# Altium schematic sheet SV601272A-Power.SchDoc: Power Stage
size 431 x 279 mm; Date: Not shown in title block; ApprovedBy: Not shown in title block; CheckedBy: Not shown in title block; Author: Not shown in title block; CompanyName: Not shown in title block; Engineer: Not shown in title block; Organization: Not shown in title block; Address1: Not shown in title block; Address2: Not shown in title block; Address3: Not shown in title block; Address4: Not shown in title block; DocumentNumber: 5; Revision: Use project parameter SCH_Rev; SheetNumber: 5; SheetTotal: 11; PageSetup: Record=PageOptions¦CenterHorizontal=True¦CenterVertical=True¦PrintScale=0.62¦XCorrection=1.00¦YCorrection=1.00¦PrintKind=0¦BorderSize=5000000¦LeftOffset=0¦BottomOffset=0¦Orientation=2¦PaperLength=1000¦PaperWidth=1000¦Scale=100¦PaperSource=15¦PrintQuality=600¦MediaType=1¦DitherType=10¦PrintScaleMode=1¦PaperKind=Letter (8.5 x 11")¦PaperIndex=1
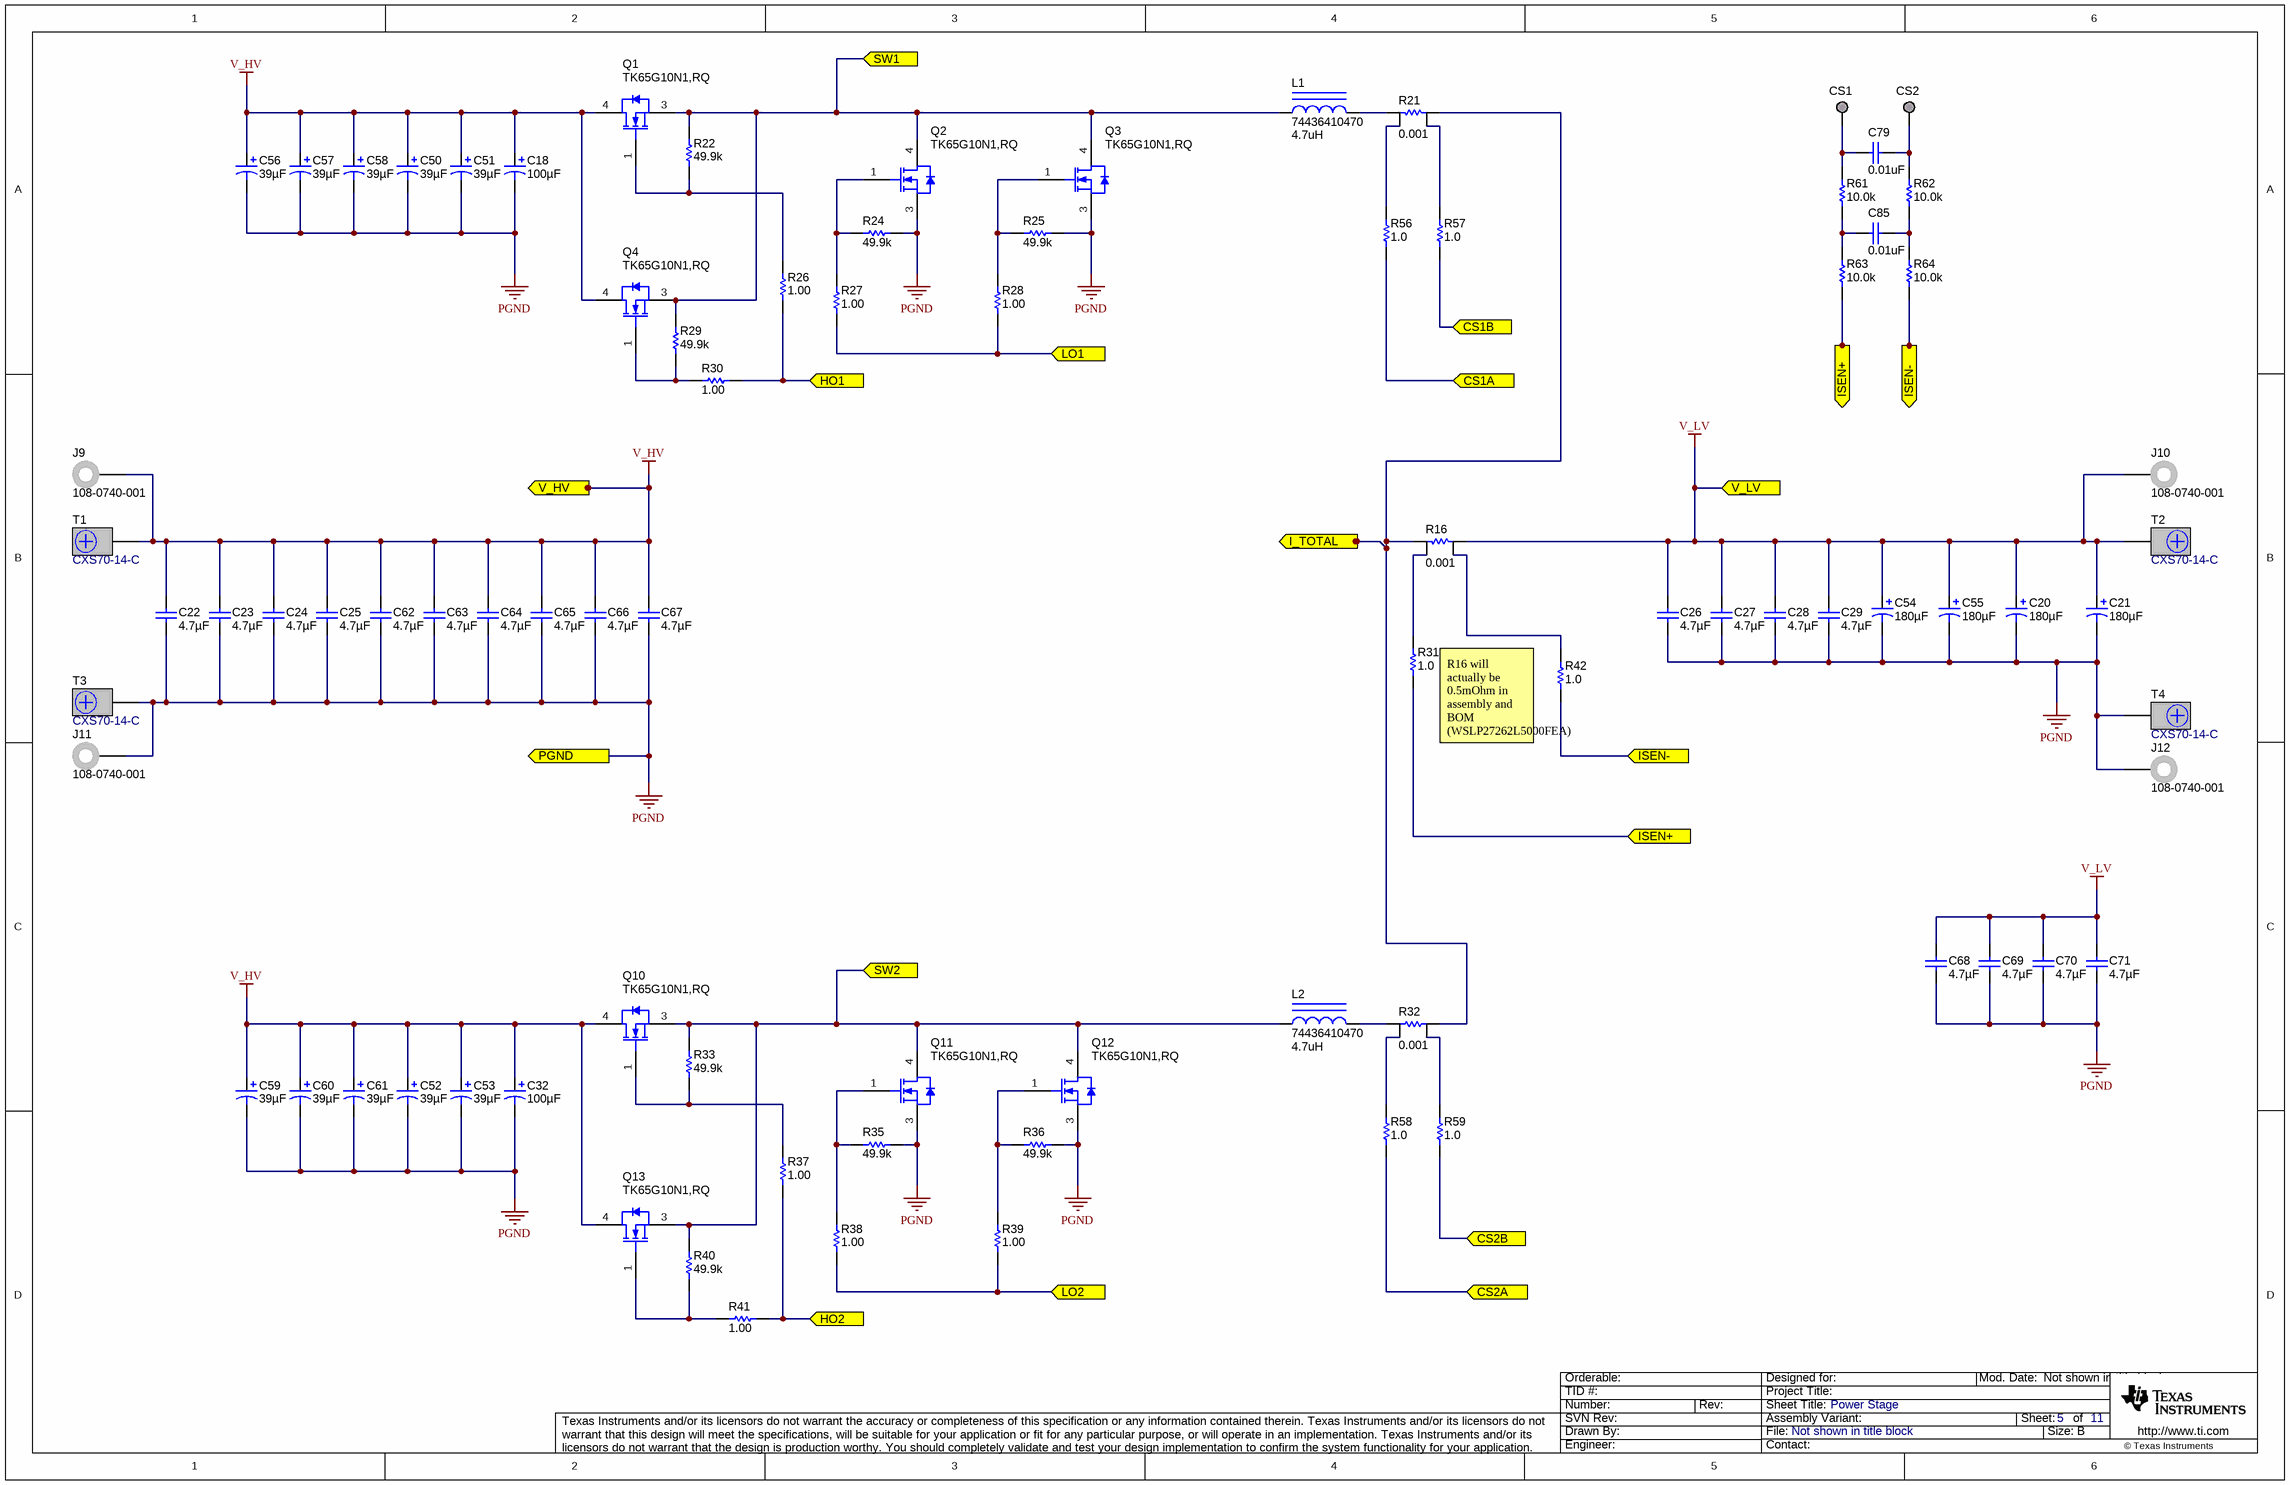
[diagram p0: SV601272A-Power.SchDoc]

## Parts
C18  ValueDisplayed: 100µF  [CAPSMT_62_LH0]  (hidden comment: EMVH101GDA101MLH0S)
C20  ValueDisplayed: 180µF  [CR_1000x1270]  (hidden comment: PCR1H181MCL1GS)
C21  ValueDisplayed: 180µF  [CR_1000x1270]  (hidden comment: PCR1H181MCL1GS)
C22  ValueDisplayed: 4.7µF  [2220_280]  (hidden comment: C5750X7R2A475M230KA)
C23  ValueDisplayed: 4.7µF  [2220_280]  (hidden comment: C5750X7R2A475M230KA)
C24  ValueDisplayed: 4.7µF  [2220_280]  (hidden comment: C5750X7R2A475M230KA)
C25  ValueDisplayed: 4.7µF  [2220_280]  (hidden comment: C5750X7R2A475M230KA)
C26  ValueDisplayed: 4.7µF  [2220_280]  (hidden comment: C5750X7R2A475M230KA)
C27  ValueDisplayed: 4.7µF  [2220_280]  (hidden comment: C5750X7R2A475M230KA)
C28  ValueDisplayed: 4.7µF  [2220_280]  (hidden comment: C5750X7R2A475M230KA)
C29  ValueDisplayed: 4.7µF  [2220_280]  (hidden comment: C5750X7R2A475M230KA)
C32  ValueDisplayed: 100µF  [CAPSMT_62_LH0]  (hidden comment: EMVH101GDA101MLH0S)
C50  ValueDisplayed: 39µF  [HXA_JA0]  (hidden comment: HHXA800ARA390MJA0G)
C51  ValueDisplayed: 39µF  [HXA_JA0]  (hidden comment: HHXA800ARA390MJA0G)
C52  ValueDisplayed: 39µF  [HXA_JA0]  (hidden comment: HHXA800ARA390MJA0G)
C53  ValueDisplayed: 39µF  [HXA_JA0]  (hidden comment: HHXA800ARA390MJA0G)
C54  ValueDisplayed: 180µF  [CR_1000x1270]  (hidden comment: PCR1H181MCL1GS)
C55  ValueDisplayed: 180µF  [CR_1000x1270]  (hidden comment: PCR1H181MCL1GS)
C56  ValueDisplayed: 39µF  [HXA_JA0]  (hidden comment: HHXA800ARA390MJA0G)
C57  ValueDisplayed: 39µF  [HXA_JA0]  (hidden comment: HHXA800ARA390MJA0G)
C58  ValueDisplayed: 39µF  [HXA_JA0]  (hidden comment: HHXA800ARA390MJA0G)
C59  ValueDisplayed: 39µF  [HXA_JA0]  (hidden comment: HHXA800ARA390MJA0G)
C60  ValueDisplayed: 39µF  [HXA_JA0]  (hidden comment: HHXA800ARA390MJA0G)
C61  ValueDisplayed: 39µF  [HXA_JA0]  (hidden comment: HHXA800ARA390MJA0G)
C62  ValueDisplayed: 4.7µF  [2220_280]  (hidden comment: C5750X7R2A475M230KA)
C63  ValueDisplayed: 4.7µF  [2220_280]  (hidden comment: C5750X7R2A475M230KA)
C64  ValueDisplayed: 4.7µF  [2220_280]  (hidden comment: C5750X7R2A475M230KA)
C65  ValueDisplayed: 4.7µF  [2220_280]  (hidden comment: C5750X7R2A475M230KA)
C66  ValueDisplayed: 4.7µF  [2220_280]  (hidden comment: C5750X7R2A475M230KA)
C67  ValueDisplayed: 4.7µF  [2220_280]  (hidden comment: C5750X7R2A475M230KA)
C68  ValueDisplayed: 4.7µF  [2220_280]  (hidden comment: C5750X7R2A475M230KA)
C69  ValueDisplayed: 4.7µF  [2220_280]  (hidden comment: C5750X7R2A475M230KA)
C70  ValueDisplayed: 4.7µF  [2220_280]  (hidden comment: C5750X7R2A475M230KA)
C71  ValueDisplayed: 4.7µF  [2220_280]  (hidden comment: C5750X7R2A475M230KA)
C79  ValueDisplayed: 0.01uF  [0603L]  (hidden comment: Capacitor)
C85  ValueDisplayed: 0.01uF  [0603L]  (hidden comment: Capacitor)
CS1  TESTPOINT  [TP_25MIL-SMT]  (value not drawn)  (no BOM)
CS2  TESTPOINT  [TP_25MIL-SMT]  (value not drawn)  (no BOM)
J9  108-0740-001  [Johnson_108-0740-001]
J10  108-0740-001  [Johnson_108-0740-001]
J11  108-0740-001  [Johnson_108-0740-001]
J12  108-0740-001  [Johnson_108-0740-001]
L1  74436410470  value 4.7uH  [WE-HCF_2818]
L2  74436410470  value 4.7uH  [WE-HCF_2818]
Q1  TK65G10N1,RQ  [DDPAK]
Q2  TK65G10N1,RQ  [DDPAK]
Q3  TK65G10N1,RQ  [DDPAK]
Q4  TK65G10N1,RQ  [DDPAK]
Q10  TK65G10N1,RQ  [DDPAK]
Q11  TK65G10N1,RQ  [DDPAK]
Q12  TK65G10N1,RQ  [DDPAK]
Q13  TK65G10N1,RQ  [DDPAK]
R16  ValueDisplayed: 0.001  [RES_WSL2726]  (hidden comment: WSLP27261L000FEA)
R21  ValueDisplayed: 0.001  [RES_WSL2726]  (hidden comment: WSL27261L000FEB)
R22  ValueDisplayed: 49.9k  [0805_HV]  (hidden comment: CRCW080549K9FKEA)
R24  ValueDisplayed: 49.9k  [0805_HV]  (hidden comment: CRCW080549K9FKEA)
R25  ValueDisplayed: 49.9k  [0805_HV]  (hidden comment: CRCW080549K9FKEA)
R26  ValueDisplayed: 1.00  [0805_HV]  (hidden comment: CRCW08051R00FKEA)
R27  ValueDisplayed: 1.00  [0805_HV]  (hidden comment: CRCW08051R00FKEA)
R28  ValueDisplayed: 1.00  [0805_HV]  (hidden comment: CRCW08051R00FKEA)
R29  ValueDisplayed: 49.9k  [0805_HV]  (hidden comment: CRCW080549K9FKEA)
R30  ValueDisplayed: 1.00  [0805_HV]  (hidden comment: CRCW08051R00FKEA)
R31  ValueDisplayed: 1.0  [0603L]  (hidden comment: CRCW06031R00JNEA)
R32  ValueDisplayed: 0.001  [RES_WSL2726]  (hidden comment: WSL27261L000FEB)
R33  ValueDisplayed: 49.9k  [0805_HV]  (hidden comment: CRCW080549K9FKEA)
R35  ValueDisplayed: 49.9k  [0805_HV]  (hidden comment: CRCW080549K9FKEA)
R36  ValueDisplayed: 49.9k  [0805_HV]  (hidden comment: CRCW080549K9FKEA)
R37  ValueDisplayed: 1.00  [0805_HV]  (hidden comment: CRCW08051R00FKEA)
R38  ValueDisplayed: 1.00  [0805_HV]  (hidden comment: CRCW08051R00FKEA)
R39  ValueDisplayed: 1.00  [0805_HV]  (hidden comment: CRCW08051R00FKEA)
R40  ValueDisplayed: 49.9k  [0805_HV]  (hidden comment: CRCW080549K9FKEA)
R41  ValueDisplayed: 1.00  [0805_HV]  (hidden comment: CRCW08051R00FKEA)
R42  ValueDisplayed: 1.0  [0603L]  (hidden comment: CRCW06031R00JNEA)
R56  ValueDisplayed: 1.0  [0603L]  (hidden comment: CRCW06031R00JNEA)
R57  ValueDisplayed: 1.0  [0603L]  (hidden comment: CRCW06031R00JNEA)
R58  ValueDisplayed: 1.0  [0603L]  (hidden comment: CRCW06031R00JNEA)
R59  ValueDisplayed: 1.0  [0603L]  (hidden comment: CRCW06031R00JNEA)
R61  ValueDisplayed: 10.0k  [0603L]  (hidden comment: Resistor)
R62  ValueDisplayed: 10.0k  [0603L]  (hidden comment: Resistor)
R63  ValueDisplayed: 10.0k  [0603L]  (hidden comment: Resistor)
R64  ValueDisplayed: 10.0k  [0603L]  (hidden comment: Resistor)
T1  CXS70-14-C  [Panduit_CXS70-14-C]
T2  CXS70-14-C  [Panduit_CXS70-14-C]
T3  CXS70-14-C  [Panduit_CXS70-14-C]
T4  CXS70-14-C  [Panduit_CXS70-14-C]

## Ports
CS1A, CS1B, CS2A, CS2B, HO1, HO2, I_TOTAL, ISEN+, ISEN-, LO1, LO2, PGND, SW1, SW2, V_HV, V_LV

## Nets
PGND: C18.2(-) C20.2(-) C21.2(-) C22.2 C23.2 C24.2 C25.2 C26.2 C27.2 C28.2 C29.2 C32.2(-) C50.2(-) C51.2(-) C52.2(-) C53.2(-) C54.2(-) C55.2(-) C56.2(-) C57.2(-) C58.2(-) C59.2(-) C60.2(-) C61.2(-) C62.2 C63.2 C64.2 C65.2 C66.2 C67.2 C68.2 C69.2 C70.2 C71.2 J11.1 J12.1 Q2.3(S) Q3.3(S) Q11.3(S) Q12.3(S) R24.2 R25.2 R35.2 R36.2 T3.1 T4.1 ; port PGND
V_HV: C18.1(+) C22.1 C23.1 C24.1 C25.1 C32.1(+) C50.1(+) C51.1(+) C52.1(+) C53.1(+) C56.1(+) C57.1(+) C58.1(+) C59.1(+) C60.1(+) C61.1(+) C62.1 C63.1 C64.1 C65.1 C66.1 C67.1 J9.1 Q1.4(D) Q4.4(D) Q10.4(D) Q13.4(D) T1.1 ; port V_HV
V_LV: C20.1(+) C21.1(+) C26.1 C27.1 C28.1 C29.1 C54.1(+) C55.1(+) C68.1 C69.1 C70.1 C71.1 J10.1 R16.2 T2.1 ; port V_LV
CS1A: R56.1 ; port CS1A
CS1B: R57.1 ; port CS1B
CS2A: R58.1 ; port CS2A
CS2B: R59.1 ; port CS2B
HO1: R26.1 R30.1 ; port HO1
HO2: R37.1 R41.1 ; port HO2
I_TOTAL: R16.1 R21.2 R32.1 ; port I_TOTAL
ISEN+: R31.1 R63.1 ; port ISEN+
ISEN-: R42.1 R64.1 ; port ISEN-
LO1: R27.1 R28.1 ; port LO1
LO2: R38.1 R39.1 ; port LO2
SW1: L1.1 Q1.3(S) Q2.4(D) Q3.4(D) Q4.3(S) R22.1 R29.1 ; port SW1
SW2: L2.2 Q10.3(S) Q11.4(D) Q12.4(D) Q13.3(S) R33.2 R40.2 ; port SW2
NetC79_1: C79.1 CS2.1 R62.2
NetC79_2: C79.2 CS1.1 R61.2
NetC85_1: C85.1 R62.1 R64.2
NetC85_2: C85.2 R61.1 R63.2
NetL1_2: L1.2 R21.1
NetL2_1: L2.1 R32.2
NetQ1_1: Q1.1(G) R22.2 R26.2
NetQ2_1: Q2.1(G) R24.1 R27.2
NetQ3_1: Q3.1(G) R25.1 R28.2
NetQ4_1: Q4.1(G) R29.2 R30.2
NetQ10_1: Q10.1(G) R33.1 R37.2
NetQ11_1: Q11.1(G) R35.1 R38.2
NetQ12_1: Q12.1(G) R36.1 R39.2
NetQ13_1: Q13.1(G) R40.1 R41.2
NetR16_3: R16.3 R31.2
NetR16_4: R16.4 R42.2
NetR21_3: R21.3 R56.2
NetR21_4: R21.4 R57.2
NetR32_3: R32.3 R59.2
NetR32_4: R32.4 R58.2

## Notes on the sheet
- R16 will actually be 0.5mOhm in assembly and BOM (WSLP27262L5000FEA)

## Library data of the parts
C18 C32 = EMVH101GDA101MLH0S: CAP, AL, 100 µF, 100 V, +/- 20%, 0.24 ohm, SMD; Manufacturer: Chemi-Con; Polarized: Y; CompType: Capacitor; Value: 100uF; U/M: EA; Cap_F: 0.0001; Tolerance_%: 20; VDC_V: 100; Value2: 100V; ESR_ohm: 0.24; IRMS_A: 0.65; TaMin_C: -40; TaMax_C: 125; Cap_Case: LH0
C20 C21 C54 C55 = PCR1H181MCL1GS: CAP, AL, 180 µF, 50 V, +/- 20%, 0.019 ohm, SMD; Manufacturer: Nichicon; Polarized: Y; CompType: Capacitor; Value: 180uF; U/M: EA; Cap_F: 0.00018; Tolerance_%: 20; VDC_V: 50; Value2: 50V; ESR_ohm: 0.019; IRMS_A: 3.5; TaMin_C: -55; TaMax_C: 125; Cap_Case: 10x12.7mm
C22-C29 C62-C71 = C5750X7R2A475M230KA: CAP, CERM, 4.7 µF, 100 V, +/- 20%, X7R, 2220; Manufacturer: TDK; Polarized: N; CompType: Capacitor; Value: 4.7uF; U/M: EA; Cap_F: 0.0000047; Tolerance_%: 20; ESR_ohm: 0.0015; Value1: 0.0015 ohm; VDC_V: 100; Value2: 100V; IRMS_A: 5.5; TaMin_C: -55; TaMax_C: 125; Cap_Case: 2220; AEC Category: Q200
C50-C53 C56-C61 = HHXA800ARA390MJA0G: CAP, Aluminum Polymer, 39 µF, 80 V, +/- 20%, 0.035 ohm, AEC-Q200 Grade 1, D10xL10mm SMD; Manufacturer: Chemi-Con; CompType: Capacitor; U/M: EA; ESR_ohm: 0.035; VDC_V: 80; Tolerance_%: 20; Value: 39uF; Polarized: Y; Cap_F: 0.000039; Value2: 80V; IRMS_A: 1.2; TaMin_C: -55; TaMax_C: 125; Cap_Case: 10X10mm; AEC Category: Q200; AEC Grade: 1
C79 C85 = CMP-0006727-4: CAP, CERM, 0.01 uF, 100 V, +/- 10%, X7R, 0603; PartNumber: 06031C103KAT2A; Manufacturer: AVX; Polarized: N; Value: 0.01uF; U/M: EA; Cap_F: 10nF; ESR_ohm: 0.098; Value1: 0.098 ohm; VDC_V: 100V; TaMin_C: -55°C; TaMax_C: 125°C; Cap_Case: 0603; AEC Category: Q200; SizeArea_mm2: 1.28; SizeAreaWB_mm2: 4.68; SizeX_mm: 1.6; SizeY_mm: 0.8; SizeZ_mm: 1
CS1 CS2 = CMP-0078143-2: TEST POINT.  No entry in BOM.
J9-J12 = 108-0740-001: Standard Banana Jack, Uninsulated, 15A; Manufacturer: Emerson Network Power; SymbolCreator: a0412235; CompType: Connector; U/M: EA
L1 L2 = 744364410470: Inductor, 4.7uH, SMT; Manufacturer: WURTH; SymbolCreator: a0413446; U/M: EA
Q1-Q4 Q10-Q13 = TK65G10N1,RQ: MOSFET N CH 100V D2PAK; Manufacturer: Toshiba Semiconductor and Storage; SymbolVersion: use current date i.e. 2008-05-20; CompType: Used in some BOM reports.  Useful for finding later.; U/M: EA, IN, or GM; SymbolCreator: Use a-id; Power - Max: 156W; Current - Continuous Drain (Id) @ 25°C: 65A (Ta); FET Type: MOSFET N-Channel, Metal Oxide; FET Feature: Standard; Vgs(th) (Max) @ Id: 4V @ 1mA; Input Capacitance (Ciss) @ Vds: 5400pF @ 50V; Rds On (Max) @ Id, Vgs: 4.5 mOhm @ 32.5A, 10V; Gate Charge (Qg) @ Vgs: 81nC @ 10V
R16 = CMP-0080414-1: RES, 0.001, 1%, 7 W, AEC-Q200 Grade 0, 6.6x3x6.9mm; Manufacturer: Vishay-Dale; Value_Code: 1L000; AEC Qualified: Y; AEC Category: Q200; Res_ohm: 1m; Value: 0.001; EIA_Code: E96; TempCo: 75 ppm/C; AEC Grade: 0; Power_W: 7W; CompType: Resistor
R21 R32 = WSL27261L000FEB: RES, 0.001, 1%, 3 W, 6.6x3x6.9mm; Manufacturer: Vishay-Dale; CompType: Resistor; U/M: EA; Tolerance_%: 1; Value: 0.001; TempCo: 75 ppm/C; Power_W: 3; Value_Code: 1L000; Value2: 3W; EIA_Code: E96; AEC Category: Q200
R22 R24 R25 R29 R33 R35 R36 R40 = CRCW080549K9FKEA: RES, 49.9 k, 1%, 0.125 W, 0805; Manufacturer: Vishay-Dale; CompType: Resistor; Value: 49.9k; Res_ohm: 49900; Value_Code: 49k9; Tolerance_%: 1; Power_W: 0.125; Value2: 0.125W; VDC_V: 150; TempCo: 100 ppm/C; EIA_Code: E96; U/M: EA
R26-R28 R30 R37-R39 R41 = CRCW08051R00FKEA: RES, 1.00, 1%, 0.125 W, 0805; Manufacturer: Vishay-Dale; CompType: Resistor; Value: 1.00; Res_ohm: 1; Value_Code: 1R00; Power_W: 0.125; Value2: 0.125W; VDC_V: 150; TempCo: 100 ppm/C; EIA_Code: E96; U/M: EA
R31 R42 R56-R59 = CRCW06031R00JNEA: RES, 1.0, 5%, 0.1 W, 0603; Manufacturer: Vishay-Dale; CompType: Resistor; Value: 1.0; Res_ohm: 1; Value_Code: 1R00; Tolerance_%: 5; Power_W: 0.1; Value2: 0.1W; VDC_V: 75; TempCo: 200 ppm/C; EIA_Code: E24; U/M: EA; AEC Category: Q200
R61-R64 = CMP-0021998-4: RES, 10.0 k, 1%, 0.1 W, AEC-Q200 Grade 0, 0603; PartNumber: CRCW060310K0FKEA; Manufacturer: Vishay-Dale; Value: 10.0k; Res_ohm: 10k; Value_Code: 10k0; Power_W: 100mW; Value2: 0.1W; VDC_V: 75V; TempCo: 100 ppm/C; EIA_Code: E96; AEC Category: Q200; AEC Qualified: Y; AEC Grade: 0; SizeArea_mm2: 1.28; SizeX_mm: 1.6; SizeY_mm: 0.8; SizeZ_mm: 1
T1-T4 = CXS70-14-C: Terminal 70A Lug; Manufacturer: Panduit; SymbolCreator: crossc; CompType: Screw Terminal; U/M: EA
